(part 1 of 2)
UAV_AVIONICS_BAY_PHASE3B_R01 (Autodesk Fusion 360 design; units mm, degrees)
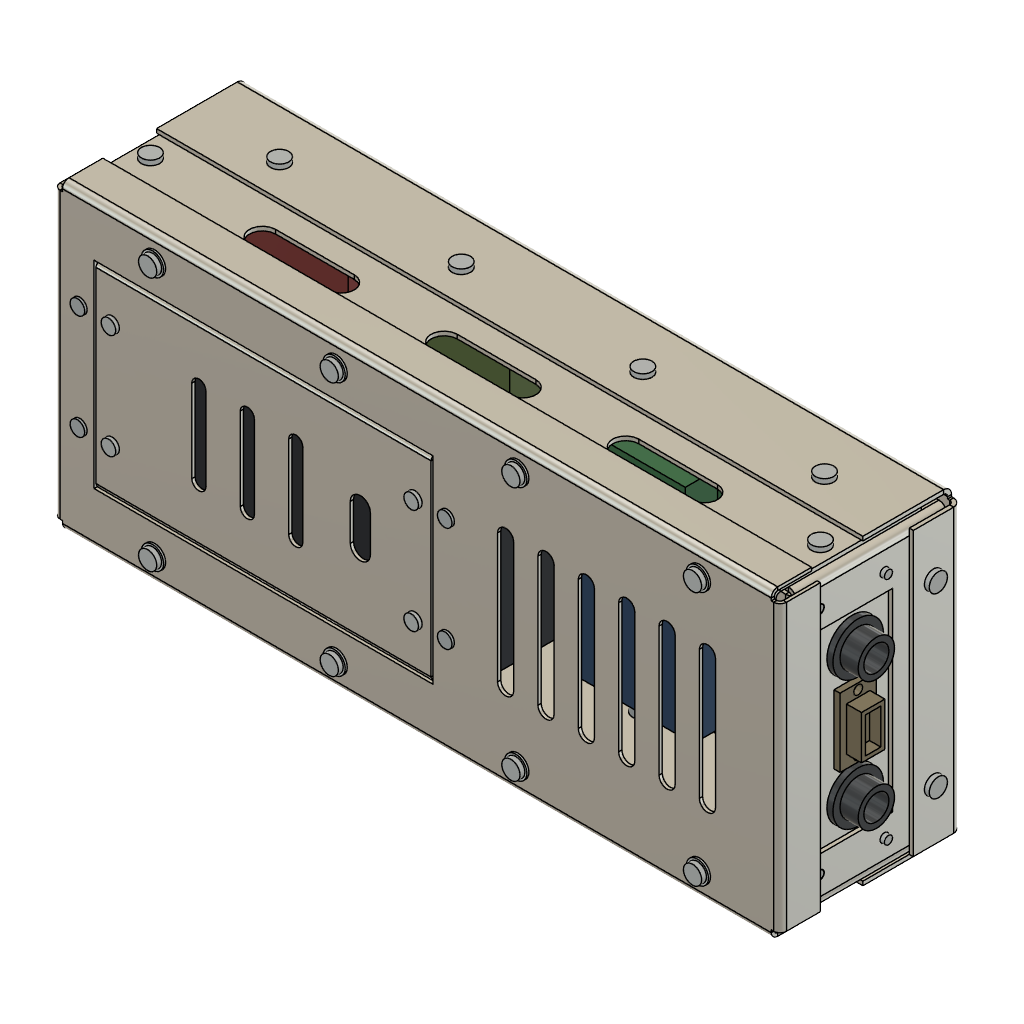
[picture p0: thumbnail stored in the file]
part number: 2026-11-24-00-18-26-593
part number: 2026-11-24-00-18-26-798
part number: 2026-11-24-00-18-26-808
part number: 2026-11-24-00-18-26-817
part number: 2026-11-24-00-18-26-829
part number: 2026-11-24-00-18-26-839
part number: 2026-11-24-00-18-26-851
part number: 2026-11-24-00-18-26-863
part number: 2026-11-24-00-18-26-875
part number: 2026-11-24-00-18-26-921
part number: 2026-11-24-00-18-27-862
part number: 2026-11-24-00-18-28-309
part number: 2026-11-24-00-18-28-832
part number: 2026-11-24-00-18-29-449
part number: 2026-11-24-00-18-30-126
part number: 2026-11-24-00-18-31-171
part number: 2026-11-24-00-18-31-826
part number: 2026-11-24-00-18-32-270
part number: 2026-11-24-00-18-33-121
part number: 2026-11-24-00-18-33-465
parameter "BAY_LENGTH" = 180 comment "[Assumption] Concept avionics bay overall outer length (X)"
parameter "BAY_WIDTH" = 75 comment "[Assumption] Concept avionics bay overall outer width (Y)"
parameter "BAY_HEIGHT" = 45 comment "[Assumption] Concept avionics bay overall outer height (Z)"
parameter "TRAY_FLANGE_H" = 22 comment "[Preliminary] Base tray perimeter upward flange height"
parameter "COVER_SKIRT_H" = 10 comment "[Preliminary] Top cover downward perimeter skirt height"
parameter "FORWARD_ZONE_END_X" = 94 comment "[Preliminary] X-boundary separating battery zone and aft deck"
parameter "HATCH_LENGTH" = 84 comment "[Preliminary] Service access hatch opening length"
parameter "HATCH_WIDTH" = 49 comment "[Preliminary] Service access hatch opening width"
parameter "T_BASE_TRAY" = 1 comment "[Preliminary] Main folded base tray thickness"
parameter "T_TOP_COVER" = 0.8 comment "[Preliminary] Removable top cover thickness"
parameter "T_ACCESS_HATCH" = 0.8 comment "[Preliminary] Service access hatch thickness"
parameter "T_SIDE_RAIL" = 1 comment "[Preliminary] Left and right side support rails thickness"
parameter "T_BULKHEAD" = 1 comment "[Preliminary] Front, rear, and connector bulkheads thickness"
parameter "T_EQUIP_DECK" = 1 comment "[Preliminary] Removable internal equipment deck thickness"
parameter "T_BRACKET" = 1 comment "[Preliminary] Structural and retention brackets thickness"
parameter "T_CABLE_CH" = 0.8 comment "[Preliminary] Cable routing channel and clamp thickness"
parameter "BEND_R_1_0" = 1 comment "[Preliminary] Inside bend radius for 1.0 mm Al 5052-H32"
parameter "BEND_R_0_8" = 0.8 comment "[Preliminary] Inside bend radius for 0.8 mm Al 5052-H32"
parameter "RELIEF_W_1_0" = 1.5 comment "[Preliminary] Bend relief width for 1.0 mm sheet"
parameter "RELIEF_D_1_0" = 2.5 comment "[Preliminary] Bend relief depth for 1.0 mm sheet"
parameter "RELIEF_W_0_8" = 1.2 comment "[Preliminary] Bend relief width for 0.8 mm sheet"
parameter "RELIEF_D_0_8" = 2.1 comment "[Preliminary] Bend relief depth for 0.8 mm sheet"
parameter "HOLE_CLR_M2_0" = 2.2 comment "[Preliminary] M2.0 medium clearance hole diameter"
parameter "HOLE_CLR_M2_5" = 2.7 comment "[Preliminary] M2.5 medium clearance hole diameter"
parameter "HOLE_CLR_M3_0" = 3.4 comment "[Preliminary] M3.0 medium clearance hole diameter"
parameter "HEAD_DIA_M2_0" = 3.8 comment "[Preliminary] ISO 4762/7380 M2.0 head diameter"
parameter "HEAD_DIA_M2_5" = 4.5 comment "[Preliminary] ISO 4762/7380 M2.5 head diameter"
parameter "STANDOFF_DECK_H" = 6 comment "[Preliminary] Under-deck plenum standoff height"
parameter "STANDOFF_PCB_H" = 4 comment "[Preliminary] PCB mounting standoff height"
parameter "ISO_PAD_THICK" = 2 comment "[Preliminary] Battery elastomer isolation pad thickness"
parameter "CLR_EQUIP_WALL" = 2 comment "[Preliminary] Minimum clearance between electronics and walls"
parameter "CLR_COMPONENT" = 1.5 comment "[Preliminary] General minimum clearance between adjacent parts"
parameter "CLR_SLIP_FIT" = 0.25 comment "[Preliminary] Per-side slip clearance for nested sheet metal parts"
parameter "CLR_COVER_FIT" = 0.3 comment "[Preliminary] Per-side clearance between cover skirt and chassis"
parameter "CLR_HATCH_GAP" = 0.5 comment "[Preliminary] Perimeter gap around removable service hatch"
parameter "d37" = 2
parameter "d38" = 1
parameter "d39" = 0.8
place_component sketch "SK_PCB_Substrate"
place_component sketch "SK_PCB_Substrate"
place_component sketch "SK_PCB_Substrate"
place_component sketch "SK_PCB_Substrate"
place_component sketch "SK_PCB_Substrate"
place_component sketch "SK_PCB_Substrate"
place_component sketch "SK_PCB_Substrate"
place_component sketch "SK_PCB_Substrate"
place_component sketch "SK_PCB_Substrate"
sketch "SK_Base_Tray_Blank" plane through (0, 0, 0) normal (0, 0, 1) x axis (1, 0, 0)
  line L1 (177.5, -37.5) -> (2.5, -37.5)
  line L2 (177.5, -35) -> (177.5, -37.5)
  line L3 (180, -35) -> (177.5, -35)
  line L4 (180, 35) -> (180, -35)
  line L5 (177.5, 35) -> (180, 35)
  line L6 (177.5, 37.5) -> (177.5, 35)
  line L7 (2.5, 37.5) -> (177.5, 37.5)
  line L8 (2.5, 35) -> (2.5, 37.5)
  line L9 (0, 35) -> (2.5, 35)
  line L10 (0, -35) -> (0, 35)
  line L11 (2.5, -35) -> (0, -35)
  line L12 (2.5, -37.5) -> (2.5, -35)
face "BaseFlange1" sketch "SK_Base_Tray_Blank"
face "EdgeFlange2" FlangeHeight 22 FlangeAngle 90
face "EdgeFlange3" FlangeHeight 12 FlangeAngle 90
sketch "SK_Base_Tray_Floor_Cutouts" plane through (0, 0, 0) normal (0, 0, 1) x axis (1, 0, 0)
  line L1 (27.3, -24.3) -> (22.7, -24.3)
  line L2 (22.7, -27.7) -> (27.3, -27.7)
  line L3 (27.3, 27.7) -> (22.7, 27.7)
  line L4 (22.7, 24.3) -> (27.3, 24.3)
  line L5 (157.3, -24.3) -> (152.7, -24.3)
  line L6 (152.7, -27.7) -> (157.3, -27.7)
  line L7 (157.3, 27.7) -> (152.7, 27.7)
  line L8 (152.7, 24.3) -> (157.3, 24.3)
  line L9 (64.5, -11.5) -> (35.5, -11.5)
  line L10 (35.5, -18.5) -> (64.5, -18.5)
  line L11 (149.5, 3.5) -> (120.5, 3.5)
  line L12 (120.5, -3.5) -> (149.5, -3.5)
  arc A1 centre (27.3, -26) radius 1.7 clockwise from (27.3, -24.3) to (27.3, -27.7)
  arc A2 centre (22.7, -26) radius 1.7 clockwise from (22.7, -27.7) to (22.7, -24.3)
  arc A3 centre (27.3, 26) radius 1.7 clockwise from (27.3, 27.7) to (27.3, 24.3)
  arc A4 centre (22.7, 26) radius 1.7 clockwise from (22.7, 24.3) to (22.7, 27.7)
  arc A5 centre (157.3, -26) radius 1.7 clockwise from (157.3, -24.3) to (157.3, -27.7)
  arc A6 centre (152.7, -26) radius 1.7 clockwise from (152.7, -27.7) to (152.7, -24.3)
  arc A7 centre (157.3, 26) radius 1.7 clockwise from (157.3, 27.7) to (157.3, 24.3)
  arc A8 centre (152.7, 26) radius 1.7 clockwise from (152.7, 24.3) to (152.7, 27.7)
  circle C1 centre (99, -29) radius 1.35
  circle C2 centre (99, 29) radius 1.35
  circle C3 centre (166, -29) radius 1.35
  circle C4 centre (166, 29) radius 1.35
  circle C5 centre (14, -27) radius 1.35
  circle C6 centre (14, -3) radius 1.35
  circle C7 centre (86, -27) radius 1.35
  circle C8 centre (86, -3) radius 1.35
  circle C9 centre (112, 12.5) radius 1.1
  circle C10 centre (152, 12.5) radius 1.1
  circle C11 centre (110, -17.5) radius 1.1
  circle C12 centre (134, -17.5) radius 1.1
  circle C13 centre (158, -17.5) radius 1.1
  circle C14 centre (13, 11) radius 1.1
  circle C15 centre (13, 27) radius 1.1
  circle C16 centre (45, 11) radius 1.1
  circle C17 centre (45, 27) radius 1.1
  circle C18 centre (57, 11) radius 1.1
  circle C19 centre (57, 27) radius 1.1
  circle C20 centre (85, 11) radius 1.1
  circle C21 centre (85, 27) radius 1.1
  arc A9 centre (64.5, -15) radius 3.5 clockwise from (64.5, -11.5) to (64.5, -18.5)
  arc A10 centre (35.5, -15) radius 3.5 clockwise from (35.5, -18.5) to (35.5, -11.5)
  arc A11 centre (149.5, 0) radius 3.5 clockwise from (149.5, 3.5) to (149.5, -3.5)
  arc A12 centre (120.5, 0) radius 3.5 clockwise from (120.5, -3.5) to (120.5, 3.5)
extrude "Extrude1" cut sketch "SK_Base_Tray_Floor_Cutouts" distance 2
work_plane "WorkPlane1" AlongDistance -37.5 ExtraOffset 0
sketch "SK_Tray_Left_Wall_Holes" plane through (0, -37.5, 0) normal (0, 1, 0) x axis (1, 0, 0)
  circle C1 centre (25, -14) radius 1.35
  circle C2 centre (70, -14) radius 1.35
  circle C3 centre (115, -14) radius 1.35
  circle C4 centre (160, -14) radius 1.35
extrude "Extrude2" cut sketch "SK_Tray_Left_Wall_Holes" distance 2
work_plane "WorkPlane2" AlongDistance 37.5 ExtraOffset 0
sketch "SK_Tray_Right_Wall_Holes" plane through (0, 37.5, 0) normal (0, 1, 0) x axis (1, 0, 0)
  circle C1 centre (25, -14) radius 1.35
  circle C2 centre (70, -14) radius 1.35
  circle C3 centre (115, -14) radius 1.35
  circle C4 centre (160, -14) radius 1.35
extrude "Extrude3" cut sketch "SK_Tray_Right_Wall_Holes" distance 2
sketch "SK_Tray_Front_Lip_Holes" plane through (0, 0, 0) normal (1, 0, 0) x axis (0, 0, -1)
  circle C1 centre (-7, -22) radius 1.35
  circle C2 centre (-7, 22) radius 1.35
extrude "Extrude4" cut sketch "SK_Tray_Front_Lip_Holes" distance 2
work_plane "WorkPlane3" AlongDistance 180 ExtraOffset 0
sketch "SK_Tray_Rear_Lip_Holes" plane through (180, 0, 0) normal (1, 0, 0) x axis (0, 0, -1)
  circle C1 centre (-7, -22) radius 1.35
  circle C2 centre (-7, 22) radius 1.35
extrude "Extrude5" cut sketch "SK_Tray_Rear_Lip_Holes" distance 2
place_component sketch "SK_PCB_Substrate"
work_plane "WorkPlane1" AlongDistance -36.35 ExtraOffset 0
sketch "SK_PDB-01-102_Left_Side_Rail_Web" plane through (0, -36.35, 0) normal (0, 1, 0) x axis (1, 0, 0)
  line L1 (177, -7) -> (3, -7)
  line L2 (177, -44) -> (177, -7)
  line L3 (3, -44) -> (177, -44)
  line L4 (3, -7) -> (3, -44)
face "BaseFlange1" sketch "SK_PDB-01-102_Left_Side_Rail_Web"
face "EdgeFlange2" FlangeHeight 9 FlangeAngle 90
sketch "SK_PDB-01-102_Left_Side_Rail_Web_Features" plane through (0, -36.35, 0) normal (0, 1, 0) x axis (1, 0, 0)
  line L1 (57.25, -34.25) -> (37.75, -34.25)
  line L2 (37.75, -27.75) -> (57.25, -27.75)
  line L3 (102.25, -34.25) -> (82.75, -34.25)
  line L4 (82.75, -27.75) -> (102.25, -27.75)
  line L5 (147.25, -34.25) -> (127.75, -34.25)
  line L6 (127.75, -27.75) -> (147.25, -27.75)
  circle C1 centre (25, -14) radius 1.35
  circle C2 centre (70, -14) radius 1.35
  circle C3 centre (115, -14) radius 1.35
  circle C4 centre (160, -14) radius 1.35
  circle C5 centre (7, -28) radius 1.35
  circle C6 centre (173, -28) radius 1.35
  arc A1 centre (57.25, -31) radius 3.25 clockwise from (57.25, -27.75) to (57.25, -34.25)
  arc A2 centre (37.75, -31) radius 3.25 clockwise from (37.75, -34.25) to (37.75, -27.75)
  arc A3 centre (102.25, -31) radius 3.25 clockwise from (102.25, -27.75) to (102.25, -34.25)
  arc A4 centre (82.75, -31) radius 3.25 clockwise from (82.75, -34.25) to (82.75, -27.75)
  arc A5 centre (147.25, -31) radius 3.25 clockwise from (147.25, -27.75) to (147.25, -34.25)
  arc A6 centre (127.75, -31) radius 3.25 clockwise from (127.75, -34.25) to (127.75, -27.75)
extrude "Extrude1" cut sketch "SK_PDB-01-102_Left_Side_Rail_Web_Features" distance 2
work_plane "WorkPlane2" AlongDistance 44 ExtraOffset 0
sketch "SK_PDB-01-102_Left_Side_Rail_Top_Holes" plane through (0, 0, 44) normal (0, 0, 1) x axis (1, 0, 0)
  circle C1 centre (25, -31.5) radius 1.35
  circle C2 centre (70, -31.5) radius 1.35
  circle C3 centre (115, -31.5) radius 1.35
  circle C4 centre (160, -31.5) radius 1.35
extrude "Extrude2" cut sketch "SK_PDB-01-102_Left_Side_Rail_Top_Holes" distance 2
place_component sketch "SK_PCB_Substrate"
work_plane "WorkPlane1" AlongDistance 36.35 ExtraOffset 0
sketch "SK_PDB-01-103_Right_Side_Rail_Web" plane through (0, 36.35, 0) normal (0, 1, 0) x axis (1, 0, 0)
  line L1 (177, -7) -> (3, -7)
  line L2 (177, -44) -> (177, -7)
  line L3 (3, -44) -> (177, -44)
  line L4 (3, -7) -> (3, -44)
face "BaseFlange2" sketch "SK_PDB-01-103_Right_Side_Rail_Web"
face "EdgeFlange3" FlangeHeight 9 FlangeAngle 90
sketch "SK_PDB-01-103_Right_Side_Rail_Web_Features" plane through (0, 36.35, 0) normal (0, 1, 0) x axis (1, 0, 0)
  line L1 (57.25, -34.25) -> (37.75, -34.25)
  line L2 (37.75, -27.75) -> (57.25, -27.75)
  line L3 (102.25, -34.25) -> (82.75, -34.25)
  line L4 (82.75, -27.75) -> (102.25, -27.75)
  line L5 (147.25, -34.25) -> (127.75, -34.25)
  line L6 (127.75, -27.75) -> (147.25, -27.75)
  circle C1 centre (25, -14) radius 1.35
  circle C2 centre (70, -14) radius 1.35
  circle C3 centre (115, -14) radius 1.35
  circle C4 centre (160, -14) radius 1.35
  circle C5 centre (7, -28) radius 1.35
  circle C6 centre (173, -28) radius 1.35
  arc A1 centre (57.25, -31) radius 3.25 clockwise from (57.25, -27.75) to (57.25, -34.25)
  arc A2 centre (37.75, -31) radius 3.25 clockwise from (37.75, -34.25) to (37.75, -27.75)
  arc A3 centre (102.25, -31) radius 3.25 clockwise from (102.25, -27.75) to (102.25, -34.25)
  arc A4 centre (82.75, -31) radius 3.25 clockwise from (82.75, -34.25) to (82.75, -27.75)
  arc A5 centre (147.25, -31) radius 3.25 clockwise from (147.25, -27.75) to (147.25, -34.25)
  arc A6 centre (127.75, -31) radius 3.25 clockwise from (127.75, -34.25) to (127.75, -27.75)
extrude "Extrude1" cut sketch "SK_PDB-01-103_Right_Side_Rail_Web_Features" distance 2
work_plane "WorkPlane2" AlongDistance 44 ExtraOffset 0
sketch "SK_PDB-01-103_Right_Side_Rail_Top_Holes" plane through (0, 0, 44) normal (0, 0, 1) x axis (1, 0, 0)
  circle C1 centre (25, 31.5) radius 1.35
  circle C2 centre (70, 31.5) radius 1.35
  circle C3 centre (115, 31.5) radius 1.35
  circle C4 centre (160, 31.5) radius 1.35
extrude "Extrude2" cut sketch "SK_PDB-01-103_Right_Side_Rail_Top_Holes" distance 2
place_component sketch "SK_PCB_Substrate"
work_plane "WorkPlane1" AlongDistance 1.15 ExtraOffset 0
sketch "SK_Front_Bulkhead_Blank" plane through (1.15, 0, 0) normal (1, 0, 0) x axis (0, 0, -1)
  line L1 (-2.5, 35.2) -> (-2.5, -35.2)
  line L2 (-39.8, 35.2) -> (-2.5, 35.2)
  line L3 (-39.8, 32.2) -> (-39.8, 35.2)
  line L4 (-42.8, 32.2) -> (-39.8, 32.2)
  line L5 (-42.8, -32.2) -> (-42.8, 32.2)
  line L6 (-39.8, -32.2) -> (-42.8, -32.2)
  line L7 (-39.8, -35.2) -> (-39.8, -32.2)
  line L8 (-2.5, -35.2) -> (-39.8, -35.2)
face "BaseFlange1" sketch "SK_Front_Bulkhead_Blank"
face "EdgeFlange2" FlangeHeight 10 FlangeAngle 90
face "EdgeFlange3" FlangeHeight 8 FlangeAngle 90
sketch "SK_Front_Bulkhead_Cutouts" plane through (1.15, 0, 0) normal (1, 0, 0) x axis (0, 0, -1)
  line L1 (-26.5, -16.5) -> (-26.5, -23.5)
  line L2 (-21.5, -23.5) -> (-21.5, -16.5)
  line L3 (-26.5, 23.5) -> (-26.5, 16.5)
  line L4 (-21.5, 16.5) -> (-21.5, 23.5)
  circle C1 centre (-7, -22) radius 1.35
  circle C2 centre (-7, 22) radius 1.35
  circle C3 centre (-24, 0) radius 5
  circle C4 centre (-24, -9) radius 1.1
  circle C5 centre (-24, 9) radius 1.1
  arc A1 centre (-24, -16.5) radius 2.5 clockwise from (-26.5, -16.5) to (-21.5, -16.5)
  arc A2 centre (-24, -23.5) radius 2.5 clockwise from (-21.5, -23.5) to (-26.5, -23.5)
  arc A3 centre (-24, 23.5) radius 2.5 clockwise from (-26.5, 23.5) to (-21.5, 23.5)
  arc A4 centre (-24, 16.5) radius 2.5 clockwise from (-21.5, 16.5) to (-26.5, 16.5)
extrude "Extrude1" cut sketch "SK_Front_Bulkhead_Cutouts" distance 2
work_plane "WorkPlane2" AlongDistance -35.2 ExtraOffset 0
sketch "SK_Front_Left_Hole" plane through (0, -35.2, 0) normal (0, 1, 0) x axis (1, 0, 0)
  circle C1 centre (7, -28) radius 1.35
extrude "Extrude2" cut sketch "SK_Front_Left_Hole" distance 2
work_plane "WorkPlane3" AlongDistance 35.2 ExtraOffset 0
sketch "SK_Front_Right_Hole" plane through (0, 35.2, 0) normal (0, 1, 0) x axis (1, 0, 0)
  circle C1 centre (7, -28) radius 1.35
extrude "Extrude3" cut sketch "SK_Front_Right_Hole" distance 2
place_component sketch "SK_PCB_Substrate"
work_plane "WorkPlane1" AlongDistance 178.85 ExtraOffset 0
sketch "SK_Rear_Bulkhead_Blank" plane through (178.85, 0, 0) normal (1, 0, 0) x axis (0, 0, -1)
  line L1 (-2.5, 35.2) -> (-2.5, -35.2)
  line L2 (-39.8, 35.2) -> (-2.5, 35.2)
  line L3 (-39.8, 32.2) -> (-39.8, 35.2)
  line L4 (-42.8, 32.2) -> (-39.8, 32.2)
  line L5 (-42.8, -32.2) -> (-42.8, 32.2)
  line L6 (-39.8, -32.2) -> (-42.8, -32.2)
  line L7 (-39.8, -35.2) -> (-39.8, -32.2)
  line L8 (-2.5, -35.2) -> (-39.8, -35.2)
face "BaseFlange2" sketch "SK_Rear_Bulkhead_Blank"
face "EdgeFlange3" FlangeHeight 10 FlangeAngle 90
face "EdgeFlange4" FlangeHeight 8 FlangeAngle 90
sketch "SK_Rear_Bulkhead_Cutouts" plane through (178.85, 0, 0) normal (1, 0, 0) x axis (0, 0, -1)
  line L1 (-16, 24) -> (-16, -24)
  line L2 (-36, 24) -> (-16, 24)
  line L3 (-36, -24) -> (-36, 24)
  line L4 (-16, -24) -> (-36, -24)
  circle C1 centre (-7, -22) radius 1.35
  circle C2 centre (-7, 22) radius 1.35
  circle C3 centre (-18, -28.5) radius 1.1
  circle C4 centre (-34, -28.5) radius 1.1
  circle C5 centre (-18, 28.5) radius 1.1
  circle C6 centre (-34, 28.5) radius 1.1
extrude "Extrude1" cut sketch "SK_Rear_Bulkhead_Cutouts" distance 2
work_plane "WorkPlane2" AlongDistance -35.2 ExtraOffset 0
sketch "SK_Rear_Left_Hole" plane through (0, -35.2, 0) normal (0, 1, 0) x axis (1, 0, 0)
  circle C1 centre (173, -28) radius 1.35
extrude "Extrude2" cut sketch "SK_Rear_Left_Hole" distance 2
work_plane "WorkPlane3" AlongDistance 35.2 ExtraOffset 0
sketch "SK_Rear_Right_Hole" plane through (0, 35.2, 0) normal (0, 1, 0) x axis (1, 0, 0)
  circle C1 centre (173, -28) radius 1.35
extrude "Extrude3" cut sketch "SK_Rear_Right_Hole" distance 2
place_component sketch "SK_PCB_Substrate"
work_plane "WorkPlane1" AlongDistance 45 ExtraOffset 0
sketch "SK_Top_Cover_Blank" plane through (0, 0, 45) normal (0, 0, 1) x axis (1, 0, 0)
  line L1 (177.8, -37.5) -> (2.2, -37.5)
  line L2 (177.8, -35.3) -> (177.8, -37.5)
  line L3 (180, -35.3) -> (177.8, -35.3)
  line L4 (180, 35.3) -> (180, -35.3)
  line L5 (177.8, 35.3) -> (180, 35.3)
  line L6 (177.8, 37.5) -> (177.8, 35.3)
  line L7 (2.2, 37.5) -> (177.8, 37.5)
  line L8 (2.2, 35.3) -> (2.2, 37.5)
  line L9 (0, 35.3) -> (2.2, 35.3)
  line L10 (0, -35.3) -> (0, 35.3)
  line L11 (2.2, -35.3) -> (0, -35.3)
  line L12 (2.2, -37.5) -> (2.2, -35.3)
face "BaseFlange2" sketch "SK_Top_Cover_Blank"
face "EdgeFlange3" FlangeHeight 10 FlangeAngle 90
face "EdgeFlange4" FlangeHeight 10 FlangeAngle 90
sketch "SK_Top_Cover_Cutouts" plane through (0, 0, 45) normal (0, 0, 1) x axis (1, 0, 0)
  line L1 (94, -24.5) -> (10, -24.5)
  line L2 (94, 24.5) -> (94, -24.5)
  line L3 (10, 24.5) -> (94, 24.5)
  line L4 (10, -24.5) -> (10, 24.5)
  line L5 (114, 16) -> (114, -16)
  line L6 (110, -16) -> (110, 16)
  line L7 (124, 16) -> (124, -16)
  line L8 (120, -16) -> (120, 16)
  line L9 (134, 16) -> (134, -16)
  line L10 (130, -16) -> (130, 16)
  line L11 (144, 16) -> (144, -16)
  line L12 (140, -16) -> (140, 16)
  line L13 (154, 16) -> (154, -16)
  line L14 (150, -16) -> (150, 16)
  line L15 (164, 16) -> (164, -16)
  line L16 (160, -16) -> (160, 16)
  circle C1 centre (25, -31.5) radius 1.35
  circle C2 centre (25, 31.5) radius 1.35
  circle C3 centre (70, -31.5) radius 1.35
  circle C4 centre (70, 31.5) radius 1.35
  circle C5 centre (115, -31.5) radius 1.35
  circle C6 centre (115, 31.5) radius 1.35
  circle C7 centre (160, -31.5) radius 1.35
  circle C8 centre (160, 31.5) radius 1.35
  circle C9 centre (6.5, -13) radius 1.1
  circle C10 centre (6.5, 13) radius 1.1
  circle C11 centre (97.5, -13) radius 1.1
  circle C12 centre (97.5, 13) radius 1.1
  arc A1 centre (112, 16) radius 2 clockwise from (110, 16) to (114, 16)
  arc A2 centre (112, -16) radius 2 clockwise from (114, -16) to (110, -16)
  arc A3 centre (122, 16) radius 2 clockwise from (120, 16) to (124, 16)
  arc A4 centre (122, -16) radius 2 clockwise from (124, -16) to (120, -16)
  arc A5 centre (132, 16) radius 2 clockwise from (130, 16) to (134, 16)
  arc A6 centre (132, -16) radius 2 clockwise from (134, -16) to (130, -16)
  arc A7 centre (142, 16) radius 2 clockwise from (140, 16) to (144, 16)
  arc A8 centre (142, -16) radius 2 clockwise from (144, -16) to (140, -16)
  arc A9 centre (152, 16) radius 2 clockwise from (150, 16) to (154, 16)
  arc A10 centre (152, -16) radius 2 clockwise from (154, -16) to (150, -16)
  arc A11 centre (162, 16) radius 2 clockwise from (160, 16) to (164, 16)
  arc A12 centre (162, -16) radius 2 clockwise from (164, -16) to (160, -16)
extrude "Extrude1" cut sketch "SK_Top_Cover_Cutouts" distance 2
place_component sketch "SK_PCB_Substrate"
work_plane "WorkPlane1" AlongDistance 45 ExtraOffset 0
sketch "SK_Access_Hatch_Blank" plane through (0, 0, 45) normal (0, 0, 1) x axis (1, 0, 0)
  line L1 (93.5, -24) -> (10.5, -24)
  line L2 (93.5, 24) -> (93.5, -24)
  line L3 (10.5, 24) -> (93.5, 24)
  line L4 (10.5, -24) -> (10.5, 24)
face "BaseFlange2" sketch "SK_Access_Hatch_Blank"
face "Hem3" HemGap 0.02 HemLength 4.5
face "Hem4" HemGap 0.02 HemLength 4.5
sketch "SK_Access_Hatch_Cutouts" plane through (0, 0, 45) normal (0, 0, 1) x axis (1, 0, 0)
  line L1 (37.75, 10.25) -> (37.75, -10.25)
  line L2 (34.25, -10.25) -> (34.25, 10.25)
  line L3 (49.75, 10.25) -> (49.75, -10.25)
  line L4 (46.25, -10.25) -> (46.25, 10.25)
  line L5 (61.75, 10.25) -> (61.75, -10.25)
  line L6 (58.25, -10.25) -> (58.25, 10.25)
  line L7 (78.5, 4.5) -> (78.5, -4.5)
  line L8 (73.5, -4.5) -> (73.5, 4.5)
  circle C1 centre (14.5, -13) radius 1.1
  circle C2 centre (14.5, 13) radius 1.1
  circle C3 centre (89.5, -13) radius 1.1
  circle C4 centre (89.5, 13) radius 1.1
  arc A1 centre (36, 10.25) radius 1.75 clockwise from (34.25, 10.25) to (37.75, 10.25)
  arc A2 centre (36, -10.25) radius 1.75 clockwise from (37.75, -10.25) to (34.25, -10.25)
  arc A3 centre (48, 10.25) radius 1.75 clockwise from (46.25, 10.25) to (49.75, 10.25)
  arc A4 centre (48, -10.25) radius 1.75 clockwise from (49.75, -10.25) to (46.25, -10.25)
  arc A5 centre (60, 10.25) radius 1.75 clockwise from (58.25, 10.25) to (61.75, 10.25)
  arc A6 centre (60, -10.25) radius 1.75 clockwise from (61.75, -10.25) to (58.25, -10.25)
  arc A7 centre (76, 4.5) radius 2.5 clockwise from (73.5, 4.5) to (78.5, 4.5)
  arc A8 centre (76, -4.5) radius 2.5 clockwise from (78.5, -4.5) to (73.5, -4.5)
extrude "Extrude1" cut sketch "SK_Access_Hatch_Cutouts" distance 2
place_component sketch "SK_PCB_Substrate"
work_plane "WorkPlane1" AlongDistance 44.2 ExtraOffset 0
sketch "SK_Retainer_Strip_Blank" plane through (0, 0, 44.2) normal (0, 0, 1) x axis (1, 0, 0)
  line L1 (18, -18) -> (3, -18)
  line L2 (18, 18) -> (18, -18)
  line L3 (3, 18) -> (18, 18)
  line L4 (3, -18) -> (3, 18)
face "BaseFlange2" sketch "SK_Retainer_Strip_Blank"
sketch "SK_Retainer_Strip_Holes" plane through (0, 0, 44.2) normal (0, 0, 1) x axis (1, 0, 0)
  circle C1 centre (6.5, -13) radius 1.1
  circle C2 centre (6.5, 13) radius 1.1
  circle C3 centre (14.5, -13) radius 1.1
  circle C4 centre (14.5, 13) radius 1.1
extrude "Extrude1" cut sketch "SK_Retainer_Strip_Holes" distance 2
copy_paste "CopyPaste1"
place_component sketch "SK_PCB_Substrate"
work_plane "WorkPlane1" AlongDistance 7 ExtraOffset 0
sketch "SK_Equipment_Deck_Blank" plane through (0, 0, 7) normal (0, 0, 1) x axis (1, 0, 0)
  line L1 (174, -33.5) -> (94, -33.5)
  line L2 (174, 33.5) -> (174, -33.5)
  line L3 (94, 33.5) -> (174, 33.5)
  line L4 (94, -33.5) -> (94, 33.5)
face "BaseFlange1" sketch "SK_Equipment_Deck_Blank"
face "EdgeFlange2" FlangeHeight 6 FlangeAngle 90
sketch "SK_Equipment_Deck_Cutouts" plane through (0, 0, 7) normal (0, 0, 1) x axis (1, 0, 0)
  line L1 (131.5, -10) -> (115.5, -10)
  line L2 (115.5, -16) -> (131.5, -16)
  line L3 (144.75, 23) -> (144.75, 11)
  line L4 (140.75, 11) -> (140.75, 23)
  circle C1 centre (99, -29) radius 1.35
  circle C2 centre (99, 29) radius 1.35
  circle C3 centre (166, -29) radius 1.35
  circle C4 centre (166, 29) radius 1.35
  circle C5 centre (106, -28) radius 1.1
  circle C6 centre (106, 2) radius 1.1
  circle C7 centre (141, -28) radius 1.1
  circle C8 centre (141, 2) radius 1.1
  circle C9 centre (105.5, 12) radius 1.1
  circle C10 centre (105.5, 28) radius 1.1
  circle C11 centre (135.5, 12) radius 1.1
  circle C12 centre (135.5, 28) radius 1.1
  circle C13 centre (150, -22) radius 1.1
  circle C14 centre (150, -4) radius 1.1
  circle C15 centre (168, -22) radius 1.1
  circle C16 centre (168, -4) radius 1.1
  circle C17 centre (150, 5) radius 1.1
  circle C18 centre (150, 23) radius 1.1
  circle C19 centre (168, 5) radius 1.1
  circle C20 centre (168, 23) radius 1.1
  arc A1 centre (131.5, -13) radius 3 clockwise from (131.5, -10) to (131.5, -16)
  arc A2 centre (115.5, -13) radius 3 clockwise from (115.5, -16) to (115.5, -10)
  arc A3 centre (142.75, 23) radius 2 clockwise from (140.75, 23) to (144.75, 23)
  arc A4 centre (142.75, 11) radius 2 clockwise from (144.75, 11) to (140.75, 11)
extrude "Extrude1" cut sketch "SK_Equipment_Deck_Cutouts" distance 2
sketch "SK_PCB_Clamp_Blank" plane through (0, 0, 0) normal (0, 0, 1) x axis (1, 0, 0)
  line L1 (3, -17.5) -> (-4, -17.5)
  line L2 (3, 17.5) -> (3, -17.5)
  line L3 (-4, 17.5) -> (3, 17.5)
  line L4 (-4, -17.5) -> (-4, 17.5)
face "BaseFlange1" sketch "SK_PCB_Clamp_Blank"
face "EdgeFlange2" FlangeHeight 6 FlangeAngle 90
sketch "SK_PCB_Clamp_Holes" plane through (0, 0, 0) normal (0, 0, 1) x axis (1, 0, 0)
  circle C1 centre (0, -15) radius 1.1
  circle C2 centre (0, 15) radius 1.1
extrude "Extrude1" cut sketch "SK_PCB_Clamp_Holes" distance 2
copy_paste "CopyPaste1"
place_component sketch "SK_PDB-03-303_Deck_Standoff_M2_5x6_Body"
sketch "SK_PDB-03-303_Deck_Standoff_M2_5x6_Body" plane through (0, 0, 0) normal (0, 0, 1) x axis (1, 0, 0)
  circle C1 centre (0, 0) radius 2.5
  circle C2 centre (0, 0) radius 1.3
extrude "Extrude1" new body sketch "SK_PDB-03-303_Deck_Standoff_M2_5x6_Body" along normal blind 6
copy_paste "CopyPaste2"
copy_paste "CopyPaste3"
copy_paste "CopyPaste4"
place_component sketch "SK_PDB-03-304_PCB_Standoff_M2x4_Body"
sketch "SK_PDB-03-304_PCB_Standoff_M2x4_Body" plane through (0, 0, 0) normal (0, 0, 1) x axis (1, 0, 0)
  circle C1 centre (0, 0) radius 2
  circle C2 centre (0, 0) radius 1.05
extrude "Extrude1" new body sketch "SK_PDB-03-304_PCB_Standoff_M2x4_Body" along normal blind 4
copy_paste "CopyPaste5"
copy_paste "CopyPaste6"
copy_paste "CopyPaste7"
copy_paste "CopyPaste8"
copy_paste "CopyPaste9"
copy_paste "CopyPaste10"
copy_paste "CopyPaste11"
copy_paste "CopyPaste12"
copy_paste "CopyPaste13"
copy_paste "CopyPaste14"
copy_paste "CopyPaste15"
copy_paste "CopyPaste16"
copy_paste "CopyPaste17"
copy_paste "CopyPaste18"
copy_paste "CopyPaste19"
copy_paste "CopyPaste20"
copy_paste "CopyPaste21"
copy_paste "CopyPaste22"
copy_paste "CopyPaste23"
copy_paste "CopyPaste24"
copy_paste "CopyPaste25"
copy_paste "CopyPaste26"
copy_paste "CopyPaste27"
place_component sketch "SK_PCB_Substrate"
work_plane "WorkPlane1" AlongDistance 5 ExtraOffset 0
sketch "SK_PCB_Substrate" plane through (0, 0, 5) normal (0, 0, 1) x axis (1, 0, 0)
  line L1 (48, 8) -> (10, 8)
  line L2 (48, 30) -> (48, 8)
  line L3 (10, 30) -> (48, 30)
  line L4 (10, 8) -> (10, 30)
extrude "Extrude1" new body sketch "SK_PCB_Substrate" along normal blind 2
work_plane "WorkPlane2" AlongDistance 7 ExtraOffset 0
sketch "SK_Module_Housing" plane through (0, 0, 7) normal (0, 0, 1) x axis (1, 0, 0)
  line L1 (43, 13) -> (15, 13)
  line L2 (43, 25) -> (43, 13)
  line L3 (15, 25) -> (43, 25)
  line L4 (15, 13) -> (15, 25)
extrude "Extrude2" add sketch "SK_Module_Housing" along normal blind 8
work_plane "WorkPlane3" AlongDistance 5 ExtraOffset 0
sketch "SK_PCB_Mount_Holes" plane through (0, 0, 5) normal (0, 0, 1) x axis (1, 0, 0)
  circle C1 centre (13, 11) radius 1.1
  circle C2 centre (13, 27) radius 1.1
  circle C3 centre (45, 11) radius 1.1
  circle C4 centre (45, 27) radius 1.1
extrude "Extrude3" cut sketch "SK_PCB_Mount_Holes" distance 3
place_component sketch "SK_PCB_Substrate"
work_plane "WorkPlane1" AlongDistance 5 ExtraOffset 0
sketch "SK_PCB_Substrate" plane through (0, 0, 5) normal (0, 0, 1) x axis (1, 0, 0)
  line L1 (88, 8) -> (54, 8)
  line L2 (88, 30) -> (88, 8)
  line L3 (54, 30) -> (88, 30)
  line L4 (54, 8) -> (54, 30)
extrude "Extrude1" new body sketch "SK_PCB_Substrate" along normal blind 2
work_plane "WorkPlane2" AlongDistance 7 ExtraOffset 0
sketch "SK_Module_Housing" plane through (0, 0, 7) normal (0, 0, 1) x axis (1, 0, 0)
  line L1 (83, 13) -> (59, 13)
  line L2 (83, 25) -> (83, 13)
  line L3 (59, 25) -> (83, 25)
  line L4 (59, 13) -> (59, 25)
extrude "Extrude2" add sketch "SK_Module_Housing" along normal blind 8
work_plane "WorkPlane3" AlongDistance 5 ExtraOffset 0
sketch "SK_PCB_Mount_Holes" plane through (0, 0, 5) normal (0, 0, 1) x axis (1, 0, 0)
  circle C1 centre (57, 11) radius 1.1
  circle C2 centre (57, 27) radius 1.1
  circle C3 centre (85, 11) radius 1.1
  circle C4 centre (85, 27) radius 1.1
extrude "Extrude3" cut sketch "SK_PCB_Mount_Holes" distance 3
place_component sketch "SK_PCB_Substrate"
work_plane "WorkPlane1" AlongDistance 12 ExtraOffset 0
sketch "SK_PCB_Substrate" plane through (0, 0, 12) normal (0, 0, 1) x axis (1, 0, 0)
  line L1 (144.5, -31) -> (102.5, -31)
  line L2 (144.5, 5) -> (144.5, -31)
  line L3 (102.5, 5) -> (144.5, 5)
  line L4 (102.5, -31) -> (102.5, 5)
extrude "Extrude1" new body sketch "SK_PCB_Substrate" along normal blind 2
work_plane "WorkPlane2" AlongDistance 14 ExtraOffset 0
sketch "SK_Module_Housing" plane through (0, 0, 14) normal (0, 0, 1) x axis (1, 0, 0)
  line L1 (137.5, -26) -> (109.5, -26)
  line L2 (137.5, 0) -> (137.5, -26)
  line L3 (109.5, 0) -> (137.5, 0)
  line L4 (109.5, -26) -> (109.5, 0)
extrude "Extrude2" add sketch "SK_Module_Housing" along normal blind 10
work_plane "WorkPlane3" AlongDistance 12 ExtraOffset 0
sketch "SK_PCB_Mount_Holes" plane through (0, 0, 12) normal (0, 0, 1) x axis (1, 0, 0)
  circle C1 centre (106, -28) radius 1.1
  circle C2 centre (106, 2) radius 1.1
  circle C3 centre (141, -28) radius 1.1
  circle C4 centre (141, 2) radius 1.1
extrude "Extrude3" cut sketch "SK_PCB_Mount_Holes" distance 3
place_component sketch "SK_PCB_Substrate"
work_plane "WorkPlane1" AlongDistance 12 ExtraOffset 0
sketch "SK_PCB_Substrate" plane through (0, 0, 12) normal (0, 0, 1) x axis (1, 0, 0)
  line L1 (138.5, 9) -> (102.5, 9)
  line L2 (138.5, 31) -> (138.5, 9)
  line L3 (102.5, 31) -> (138.5, 31)
  line L4 (102.5, 9) -> (102.5, 31)
extrude "Extrude1" new body sketch "SK_PCB_Substrate" along normal blind 2
work_plane "WorkPlane2" AlongDistance 14 ExtraOffset 0
sketch "SK_Module_Housing" plane through (0, 0, 14) normal (0, 0, 1) x axis (1, 0, 0)
  line L1 (133.5, 14) -> (107.5, 14)
  line L2 (133.5, 26) -> (133.5, 14)
  line L3 (107.5, 26) -> (133.5, 26)
  line L4 (107.5, 14) -> (107.5, 26)
extrude "Extrude2" add sketch "SK_Module_Housing" along normal blind 8
work_plane "WorkPlane3" AlongDistance 12 ExtraOffset 0
sketch "SK_PCB_Mount_Holes" plane through (0, 0, 12) normal (0, 0, 1) x axis (1, 0, 0)
  circle C1 centre (105.5, 12) radius 1.1
  circle C2 centre (105.5, 28) radius 1.1
  circle C3 centre (135.5, 12) radius 1.1
  circle C4 centre (135.5, 28) radius 1.1
extrude "Extrude3" cut sketch "SK_PCB_Mount_Holes" distance 3
place_component sketch "SK_PCB_Substrate"
work_plane "WorkPlane1" AlongDistance 12 ExtraOffset 0
sketch "SK_PCB_Substrate" plane through (0, 0, 12) normal (0, 0, 1) x axis (1, 0, 0)
  line L1 (171, -25) -> (147, -25)
  line L2 (171, -1) -> (171, -25)
  line L3 (147, -1) -> (171, -1)
  line L4 (147, -25) -> (147, -1)
extrude "Extrude1" new body sketch "SK_PCB_Substrate" along normal blind 2
work_plane "WorkPlane2" AlongDistance 14 ExtraOffset 0
sketch "SK_Module_Housing" plane through (0, 0, 14) normal (0, 0, 1) x axis (1, 0, 0)
  line L1 (166, -20) -> (152, -20)
  line L2 (166, -6) -> (166, -20)
  line L3 (152, -6) -> (166, -6)
  line L4 (152, -20) -> (152, -6)
extrude "Extrude2" add sketch "SK_Module_Housing" along normal blind 7
work_plane "WorkPlane3" AlongDistance 12 ExtraOffset 0
sketch "SK_PCB_Mount_Holes" plane through (0, 0, 12) normal (0, 0, 1) x axis (1, 0, 0)
  circle C1 centre (150, -22) radius 1.1
  circle C2 centre (150, -4) radius 1.1
  circle C3 centre (168, -22) radius 1.1
  circle C4 centre (168, -4) radius 1.1
extrude "Extrude3" cut sketch "SK_PCB_Mount_Holes" distance 3
place_component sketch "SK_PCB_Substrate"
work_plane "WorkPlane1" AlongDistance 12 ExtraOffset 0
sketch "SK_PCB_Substrate" plane through (0, 0, 12) normal (0, 0, 1) x axis (1, 0, 0)
  line L1 (171, 2) -> (147, 2)
  line L2 (171, 26) -> (171, 2)
  line L3 (147, 26) -> (171, 26)
  line L4 (147, 2) -> (147, 26)
extrude "Extrude1" new body sketch "SK_PCB_Substrate" along normal blind 2
work_plane "WorkPlane2" AlongDistance 14 ExtraOffset 0
sketch "SK_Module_Housing" plane through (0, 0, 14) normal (0, 0, 1) x axis (1, 0, 0)
  line L1 (166, 7) -> (152, 7)
  line L2 (166, 21) -> (166, 7)
  line L3 (152, 21) -> (166, 21)
  line L4 (152, 7) -> (152, 21)
extrude "Extrude2" add sketch "SK_Module_Housing" along normal blind 6
work_plane "WorkPlane3" AlongDistance 12 ExtraOffset 0
sketch "SK_PCB_Mount_Holes" plane through (0, 0, 12) normal (0, 0, 1) x axis (1, 0, 0)
  circle C1 centre (150, 5) radius 1.1
  circle C2 centre (150, 23) radius 1.1
  circle C3 centre (168, 5) radius 1.1
  circle C4 centre (168, 23) radius 1.1
extrude "Extrude3" cut sketch "SK_PCB_Mount_Holes" distance 3
place_component sketch "SK_PCB_Substrate"
work_plane "WorkPlane1" AlongDistance 3 ExtraOffset 0
sketch "SK_Battery_Envelope_Solid" plane through (0, 0, 3) normal (0, 0, 1) x axis (1, 0, 0)
  line L1 (92, -32) -> (8, -32)
  line L2 (92, 2) -> (92, -32)
  line L3 (8, 2) -> (92, 2)
  line L4 (8, -32) -> (8, 2)
extrude "Extrude1" new body sketch "SK_Battery_Envelope_Solid" along normal blind 24
sketch "SK_Battery_Cradle_Blank" plane through (0, 0, 0) normal (0, 0, 1) x axis (1, 0, 0)
  line L1 (4, -18.2) -> (-4, -18.2)
  line L2 (4, 18.2) -> (4, -18.2)
  line L3 (-4, 18.2) -> (4, 18.2)
  line L4 (-4, -18.2) -> (-4, 18.2)
face "BaseFlange1" sketch "SK_Battery_Cradle_Blank"
face "EdgeFlange2" FlangeHeight 27 FlangeAngle 90
sketch "SK_Cradle_Floor_Holes" plane through (0, 0, 0) normal (0, 0, 1) x axis (1, 0, 0)
  circle C1 centre (0, -12) radius 1.35
  circle C2 centre (0, 12) radius 1.35
extrude "Extrude1" cut sketch "SK_Cradle_Floor_Holes" distance 2
work_plane "WorkPlane1" AlongDistance -18.2 ExtraOffset 0
sketch "SK_Cradle_Left_Slot" plane through (0, -18.2, 0) normal (0, 1, 0) x axis (1, 0, 0)
  line L1 (1.6, -19.9) -> (1.6, -9.1)
  line L2 (-1.6, -9.1) -> (-1.6, -19.9)
  arc A1 centre (0, -19.9) radius 1.6 clockwise from (1.6, -19.9) to (-1.6, -19.9)
  arc A2 centre (0, -9.1) radius 1.6 clockwise from (-1.6, -9.1) to (1.6, -9.1)
extrude "Extrude2" cut sketch "SK_Cradle_Left_Slot" distance 2
work_plane "WorkPlane2" AlongDistance 18.2 ExtraOffset 0
sketch "SK_Cradle_Right_Slot" plane through (0, 18.2, 0) normal (0, 1, 0) x axis (1, 0, 0)
  line L1 (1.6, -19.9) -> (1.6, -9.1)
  line L2 (-1.6, -9.1) -> (-1.6, -19.9)
  arc A1 centre (0, -19.9) radius 1.6 clockwise from (1.6, -19.9) to (-1.6, -19.9)
  arc A2 centre (0, -9.1) radius 1.6 clockwise from (-1.6, -9.1) to (1.6, -9.1)
extrude "Extrude3" cut sketch "SK_Cradle_Right_Slot" distance 2
copy_paste "CopyPaste1"
place_component sketch "SK_PCB_Substrate"
work_plane "WorkPlane1" AlongDistance 1 ExtraOffset 0
sketch "SK_Isolation_Pad_Body" plane through (0, 0, 1) normal (0, 0, 1) x axis (1, 0, 0)
  line L1 (81, -31) -> (19, -31)
  line L2 (81, 1) -> (81, -31)
  line L3 (19, 1) -> (81, 1)
  line L4 (19, -31) -> (19, 1)
extrude "Extrude1" new body sketch "SK_Isolation_Pad_Body" along normal blind 2
work_plane "WorkPlane2" AlongDistance 1 ExtraOffset 0
sketch "SK_Iso_Pad_Vent_Slot" plane through (0, 0, 1) normal (0, 0, 1) x axis (1, 0, 0)
  line L1 (64, -12) -> (36, -12)
  line L2 (36, -18) -> (64, -18)
  arc A1 centre (64, -15) radius 3 clockwise from (64, -12) to (64, -18)
  arc A2 centre (36, -15) radius 3 clockwise from (36, -18) to (36, -12)
extrude "Extrude2" cut sketch "SK_Iso_Pad_Vent_Slot" distance 3
work_plane "WorkPlane1" AlongDistance -2.5 ExtraOffset 0
sketch "SK_Retention_Strap_U" plane through (-2.5, 0, 0) normal (1, 0, 0) x axis (0, 0, -1)
  line L1 (-13.5, -18.3) -> (-13.5, -19.3)
  line L2 (-27.2, -18.3) -> (-13.5, -18.3)
  line L3 (-27.2, 18.3) -> (-27.2, -18.3)
  line L4 (-13.5, 18.3) -> (-27.2, 18.3)
  line L5 (-13.5, 19.3) -> (-13.5, 18.3)
  line L6 (-28.2, 19.3) -> (-13.5, 19.3)
  line L7 (-28.2, -19.3) -> (-28.2, 19.3)
  line L8 (-13.5, -19.3) -> (-28.2, -19.3)
extrude "Extrude1" new body sketch "SK_Retention_Strap_U" along normal blind 5
copy_paste "CopyPaste2"
place_component sketch "SK_PCB_Substrate"
work_plane "WorkPlane1" AlongDistance 177.85 ExtraOffset 0
sketch "SK_Connector_Plate_Blank" plane through (177.85, 0, 0) normal (1, 0, 0) x axis (0, 0, -1)
  line L1 (-14, 33) -> (-14, -33)
  line L2 (-38.5, 33) -> (-14, 33)
  line L3 (-38.5, -33) -> (-38.5, 33)
  line L4 (-14, -33) -> (-38.5, -33)
face "BaseFlange2" sketch "SK_Connector_Plate_Blank"
sketch "SK_Connector_Plate_Cutouts" plane through (177.85, 0, 0) normal (1, 0, 0) x axis (0, 0, -1)
  line L1 (-22, 5.5) -> (-22, -5.5)
  line L2 (-28, 5.5) -> (-22, 5.5)
  line L3 (-28, -5.5) -> (-28, 5.5)
  line L4 (-22, -5.5) -> (-28, -5.5)
  circle C1 centre (-18, -28.5) radius 1.1
  circle C2 centre (-34, -28.5) radius 1.1
  circle C3 centre (-18, 28.5) radius 1.1
  circle C4 centre (-34, 28.5) radius 1.1
  circle C5 centre (-25, -16) radius 4.5
  circle C6 centre (-25, 16) radius 4.5
  circle C7 centre (-25, -7) radius 1.1
  circle C8 centre (-25, 7) radius 1.1
extrude "Extrude1" cut sketch "SK_Connector_Plate_Cutouts" distance 2
sketch "SK_Conn_Flange" plane through (0, 0, 0) normal (0, 0, 1) x axis (1, 0, 0)
  circle C1 centre (0, 0) radius 6.25
extrude "Extrude1" new body sketch "SK_Conn_Flange" along a picked direction blind 1.5
work_plane "WorkPlane1" AlongDistance -2.6 ExtraOffset 0
sketch "SK_Conn_Rear_Body" plane through (0, 0, -2.6) normal (0, 0, 1) x axis (1, 0, 0)
  circle C1 centre (0, 0) radius 4.4
extrude "Extrude2" add sketch "SK_Conn_Rear_Body" along a picked direction blind 2.6
work_plane "WorkPlane2" AlongDistance 1.5 ExtraOffset 0
sketch "SK_Conn_Mating_Barrel" plane through (0, 0, 1.5) normal (0, 0, 1) x axis (1, 0, 0)
  circle C1 centre (0, 0) radius 4.5
  circle C2 centre (0, 0) radius 3.1
extrude "Extrude3" add sketch "SK_Conn_Mating_Barrel" along a picked direction blind 4.5
copy_paste "CopyPaste1"
place_component sketch "SK_PCB_Substrate"
work_plane "WorkPlane1" AlongDistance 20.5 ExtraOffset 0
sketch "SK_MicroD_Flange" plane through (0, 0, 20.5) normal (0, 0, 1) x axis (1, 0, 0)
  line L1 (179.35, -8.5) -> (177.85, -8.5)
  line L2 (179.35, 8.5) -> (179.35, -8.5)
  line L3 (177.85, 8.5) -> (179.35, 8.5)
  line L4 (177.85, -8.5) -> (177.85, 8.5)
extrude "Extrude1" new body sketch "SK_MicroD_Flange" along normal blind 9
work_plane "WorkPlane2" AlongDistance 22.1 ExtraOffset 0
sketch "SK_MicroD_Rear_Body" plane through (0, 0, 22.1) normal (0, 0, 1) x axis (1, 0, 0)
  line L1 (177.85, -5.4) -> (175.25, -5.4)
  line L2 (177.85, 5.4) -> (177.85, -5.4)
  line L3 (175.25, 5.4) -> (177.85, 5.4)
  line L4 (175.25, -5.4) -> (175.25, 5.4)
extrude "Extrude2" add sketch "SK_MicroD_Rear_Body" along normal blind 5.8
work_plane "WorkPlane3" AlongDistance 22.1 ExtraOffset 0
sketch "SK_MicroD_Shroud" plane through (0, 0, 22.1) normal (0, 0, 1) x axis (1, 0, 0)
  line L1 (183.05, -5.4) -> (179.35, -5.4)
  line L2 (183.05, 5.4) -> (183.05, -5.4)
  line L3 (179.35, 5.4) -> (183.05, 5.4)
  line L4 (179.35, -5.4) -> (179.35, 5.4)
extrude "Extrude3" add sketch "SK_MicroD_Shroud" along normal blind 5.8
work_plane "WorkPlane4" AlongDistance 23.1 ExtraOffset 0
sketch "SK_MicroD_Pin_Pocket" plane through (0, 0, 23.1) normal (0, 0, 1) x axis (1, 0, 0)
  line L1 (183.45, -4.4) -> (180.25, -4.4)
  line L2 (183.45, 4.4) -> (183.45, -4.4)
  line L3 (180.25, 4.4) -> (183.45, 4.4)
  line L4 (180.25, -4.4) -> (180.25, 4.4)
extrude "Extrude4" cut sketch "SK_MicroD_Pin_Pocket" along normal blind 3.8
work_plane "WorkPlane5" AlongDistance 177.85 ExtraOffset 0
sketch "SK_MicroD_Jackposts" plane through (177.85, 0, 0) normal (1, 0, 0) x axis (0, 0, -1)
  circle C1 centre (-25, -7) radius 1.1
  circle C2 centre (-25, 7) radius 1.1
extrude "Extrude5" cut sketch "SK_MicroD_Jackposts" distance 2.5
place_component sketch "SK_PCB_Substrate"
work_plane "WorkPlane1" AlongDistance 176.85 ExtraOffset 0
sketch "SK_Strain_Relief_Blank" plane through (176.85, 0, 0) normal (1, 0, 0) x axis (0, 0, -1)
  line L1 (-31.8, 32) -> (-31.8, -32)
  line L2 (-38.5, 32) -> (-31.8, 32)
  line L3 (-38.5, -32) -> (-38.5, 32)
  line L4 (-31.8, -32) -> (-38.5, -32)
face "BaseFlange2" sketch "SK_Strain_Relief_Blank"
face "EdgeFlange3" FlangeHeight 8 FlangeAngle 90
sketch "SK_Strain_Relief_Mount_Holes" plane through (176.85, 0, 0) normal (1, 0, 0) x axis (0, 0, -1)
  circle C1 centre (-34, -28.5) radius 1.1
  circle C2 centre (-34, 28.5) radius 1.1
extrude "Extrude1" cut sketch "SK_Strain_Relief_Mount_Holes" distance 2
work_plane "WorkPlane2" AlongDistance 38.5 ExtraOffset 0
sketch "SK_Strain_Relief_Tie_Slots" plane through (0, 0, 38.5) normal (0, 0, 1) x axis (1, 0, 0)
  line L1 (173.25, -14.25) -> (173.25, -17.75)
  line L2 (170.75, -17.75) -> (170.75, -14.25)
  line L3 (173.25, 1.75) -> (173.25, -1.75)
  line L4 (170.75, -1.75) -> (170.75, 1.75)
  line L5 (173.25, 17.75) -> (173.25, 14.25)
  line L6 (170.75, 14.25) -> (170.75, 17.75)
  arc A1 centre (172, -14.25) radius 1.25 clockwise from (170.75, -14.25) to (173.25, -14.25)
  arc A2 centre (172, -17.75) radius 1.25 clockwise from (173.25, -17.75) to (170.75, -17.75)
  arc A3 centre (172, 1.75) radius 1.25 clockwise from (170.75, 1.75) to (173.25, 1.75)
  arc A4 centre (172, -1.75) radius 1.25 clockwise from (173.25, -1.75) to (170.75, -1.75)
  arc A5 centre (172, 17.75) radius 1.25 clockwise from (170.75, 17.75) to (173.25, 17.75)
  arc A6 centre (172, 14.25) radius 1.25 clockwise from (173.25, 14.25) to (170.75, 14.25)
extrude "Extrude2" cut sketch "SK_Strain_Relief_Tie_Slots" distance 2
place_component sketch "SK_PCB_Substrate"
work_plane "WorkPlane1" AlongDistance 1 ExtraOffset 0
sketch "SK_Cable_Channel_Blank" plane through (0, 0, 1) normal (0, 0, 1) x axis (1, 0, 0)
  line L1 (166, 8.5) -> (98, 8.5)
  line L2 (166, 21.5) -> (166, 8.5)
  line L3 (98, 21.5) -> (166, 21.5)
  line L4 (98, 8.5) -> (98, 21.5)
face "BaseFlange1" sketch "SK_Cable_Channel_Blank"
face "EdgeFlange2" FlangeHeight 5 FlangeAngle 90
sketch "SK_Cable_Channel_Holes" plane through (0, 0, 1) normal (0, 0, 1) x axis (1, 0, 0)
  circle C1 centre (112, 12.5) radius 1.1
  circle C2 centre (152, 12.5) radius 1.1
extrude "Extrude1" cut sketch "SK_Cable_Channel_Holes" distance 2
sketch "SK_Cable_Clamp_Blank" plane through (0, 0, 0) normal (0, 0, 1) x axis (1, 0, 0)
  line L1 (3.5, -6.5) -> (-3.5, -6.5)
  line L2 (3.5, 4.5) -> (3.5, -6.5)
  line L3 (-3.5, 4.5) -> (3.5, 4.5)
  line L4 (-3.5, -6.5) -> (-3.5, 4.5)
face "BaseFlange1" sketch "SK_Cable_Clamp_Blank"
face "EdgeFlange2" FlangeHeight 5 FlangeAngle 90
face "EdgeFlange3" FlangeHeight 5 FlangeAngle 90
sketch "SK_Cable_Clamp_Hole" plane through (0, 0, 0) normal (0, 0, 1) x axis (1, 0, 0)
  circle C1 centre (0, -2.5) radius 1.1
extrude "Extrude1" cut sketch "SK_Cable_Clamp_Hole" distance 2
copy_paste "CopyPaste1"
copy_paste "CopyPaste2"
place_component sketch "SK_PCB_Substrate"
work_plane "WorkPlane1" AlongDistance 17.5 ExtraOffset 0
sketch "SK_PDB-07-703_Power_Harness_Visual_Path" plane through (0, 17.5, 0) normal (0, 1, 0) x axis (1, 0, 0)
  line L1 (171.2, -3.2) -> (48.5, -3.2)
  line L2 (175.2, -20.4) -> (175.2, -7.2)
  arc A1 centre (171.2, -7.2) radius 4 clockwise from (171.2, -3.2) to (175.2, -7.2)
work_plane "WorkPlane2" AlongDistance 48.5 ExtraOffset 0
sketch "SK_PDB-07-703_Power_Harness_Visual_Profile" plane through (48.5, 0, 0) normal (1, 0, 0) x axis (0, 0, -1)
  circle C1 centre (-3.2, 17.5) radius 1
sweep "Sweep1" sketch "SK_PDB-07-703_Power_Harness_Visual_Profile" TwistAngle 0 TaperAngle 0
place_component sketch "SK_PCB_Substrate"
work_plane "WorkPlane1" AlongDistance -13.5 ExtraOffset 0
sketch "SK_PDB-07-704_Signal_Harness_Visual_Path" plane through (0, -13.5, 0) normal (0, 1, 0) x axis (1, 0, 0)
  line L1 (171.2, -3) -> (104, -3)
  line L2 (175.2, -20.4) -> (175.2, -7)
  arc A1 centre (171.2, -7) radius 4 clockwise from (171.2, -3) to (175.2, -7)
work_plane "WorkPlane2" AlongDistance 104 ExtraOffset 0
sketch "SK_PDB-07-704_Signal_Harness_Visual_Profile" plane through (104, 0, 0) normal (1, 0, 0) x axis (0, 0, -1)
  circle C1 centre (-3, -13.5) radius 1
sweep "Sweep1" sketch "SK_PDB-07-704_Signal_Harness_Visual_Profile" TwistAngle 0 TaperAngle 0
sketch "SK_Fastener_Head" plane through (0, 0, 0) normal (0, 0, 1) x axis (1, 0, 0)
  circle C1 centre (0, 0) radius 2.25
extrude "Extrude1" new body sketch "SK_Fastener_Head" along a picked direction blind 1.2
sketch "SK_Fastener_Shank" plane through (0, 0, 0) normal (0, 0, 1) x axis (1, 0, 0)
  circle C1 centre (0, 0) radius 1.25
extrude "Extrude2" add sketch "SK_Fastener_Shank" along a picked direction blind -5
copy_paste "CopyPaste1"
copy_paste "CopyPaste2"
copy_paste "CopyPaste3"
copy_paste "CopyPaste4"
copy_paste "CopyPaste5"
copy_paste "CopyPaste6"
copy_paste "CopyPaste7"
copy_paste "CopyPaste8"
copy_paste "CopyPaste9"
copy_paste "CopyPaste10"
copy_paste "CopyPaste11"
copy_paste "CopyPaste12"
copy_paste "CopyPaste13"
copy_paste "CopyPaste14"
copy_paste "CopyPaste15"
copy_paste "CopyPaste16"
copy_paste "CopyPaste17"
copy_paste "CopyPaste18"
copy_paste "CopyPaste19"
copy_paste "CopyPaste20"
copy_paste "CopyPaste21"
copy_paste "CopyPaste22"
copy_paste "CopyPaste23"
copy_paste "CopyPaste24"
copy_paste "CopyPaste25"
copy_paste "CopyPaste26"
copy_paste "CopyPaste27"
copy_paste "CopyPaste28"
copy_paste "CopyPaste29"
copy_paste "CopyPaste30"
copy_paste "CopyPaste31"
place_component sketch "SK_Hardware_Ring"
sketch "SK_Hardware_Ring" plane through (0, 0, 0) normal (0, 0, 1) x axis (1, 0, 0)
  circle C1 centre (0, 0) radius 2.75
  circle C2 centre (0, 0) radius 1.35
extrude "Extrude1" new body sketch "SK_Hardware_Ring" along normal blind 0.5
copy_paste "CopyPaste32"
copy_paste "CopyPaste33"
copy_paste "CopyPaste34"
copy_paste "CopyPaste35"
copy_paste "CopyPaste36"
copy_paste "CopyPaste37"
copy_paste "CopyPaste38"
copy_paste "CopyPaste39"
copy_paste "CopyPaste40"
copy_paste "CopyPaste41"
copy_paste "CopyPaste42"
place_component sketch "SK_Hardware_Ring"
sketch "SK_Hardware_Ring" plane through (0, 0, 0) normal (0, 0, 1) x axis (1, 0, 0)
  circle C1 centre (0, 0) radius 2.5
  circle C2 centre (0, 0) radius 1.25
extrude "Extrude1" new body sketch "SK_Hardware_Ring" along a picked direction blind 2
copy_paste "CopyPaste43"
copy_paste "CopyPaste44"
copy_paste "CopyPaste45"
copy_paste "CopyPaste46"
copy_paste "CopyPaste47"
copy_paste "CopyPaste48"
copy_paste "CopyPaste49"
copy_paste "CopyPaste50"
copy_paste "CopyPaste51"
copy_paste "CopyPaste52"
copy_paste "CopyPaste53"
copy_paste "CopyPaste54"
copy_paste "CopyPaste55"
copy_paste "CopyPaste56"
copy_paste "CopyPaste57"
copy_paste "CopyPaste58"
copy_paste "CopyPaste59"
copy_paste "CopyPaste60"
copy_paste "CopyPaste61"
copy_paste "CopyPaste62"
copy_paste "CopyPaste63"
copy_paste "CopyPaste64"
copy_paste "CopyPaste65"
sketch "SK_Fastener_Head" plane through (0, 0, 0) normal (0, 0, 1) x axis (1, 0, 0)
  circle C1 centre (0, 0) radius 1.8
extrude "Extrude1" new body sketch "SK_Fastener_Head" along normal blind 0.9
sketch "SK_Fastener_Shank" plane through (0, 0, 0) normal (0, 0, 1) x axis (1, 0, 0)
  circle C1 centre (0, 0) radius 1
extrude "Extrude2" add sketch "SK_Fastener_Shank" against normal blind 4
copy_paste "CopyPaste66"
copy_paste "CopyPaste67"
copy_paste "CopyPaste68"
copy_paste "CopyPaste69"
copy_paste "CopyPaste70"
copy_paste "CopyPaste71"
copy_paste "CopyPaste72"
copy_paste "CopyPaste73"
copy_paste "CopyPaste74"
copy_paste "CopyPaste75"
copy_paste "CopyPaste76"
copy_paste "CopyPaste77"
copy_paste "CopyPaste78"
copy_paste "CopyPaste79"
copy_paste "CopyPaste80"
copy_paste "CopyPaste81"
copy_paste "CopyPaste82"
copy_paste "CopyPaste83"
copy_paste "CopyPaste84"
copy_paste "CopyPaste85"
copy_paste "CopyPaste86"
copy_paste "CopyPaste87"
copy_paste "CopyPaste88"
place_component sketch "SK_Hardware_Ring"
sketch "SK_Hardware_Ring" plane through (0, 0, 0) normal (0, 0, 1) x axis (1, 0, 0)
  circle C1 centre (0, 0) radius 2.25
  circle C2 centre (0, 0) radius 1.05
extrude "Extrude1" new body sketch "SK_Hardware_Ring" along normal blind 0.8
copy_paste "CopyPaste89"
copy_paste "CopyPaste90"
copy_paste "CopyPaste91"
copy_paste "CopyPaste92"
copy_paste "CopyPaste93"
copy_paste "CopyPaste94"
copy_paste "CopyPaste95"
sketch "SK_Fastener_Head" plane through (0, 0, 0) normal (0, 0, 1) x axis (1, 0, 0)
  circle C1 centre (0, 0) radius 1.8
extrude "Extrude1" new body sketch "SK_Fastener_Head" along normal blind 0.9
sketch "SK_Fastener_Shank" plane through (0, 0, 0) normal (0, 0, 1) x axis (1, 0, 0)
  circle C1 centre (0, 0) radius 1
extrude "Extrude2" add sketch "SK_Fastener_Shank" against normal blind 3
copy_paste "CopyPaste96"
copy_paste "CopyPaste97"
copy_paste "CopyPaste98"
copy_paste "CopyPaste99"
copy_paste "CopyPaste100"
copy_paste "CopyPaste101"
copy_paste "CopyPaste102"
sketch "SK_Fastener_Head" plane through (0, 0, 0) normal (0, 0, 1) x axis (1, 0, 0)
  circle C1 centre (0, 0) radius 1.8
extrude "Extrude1" new body sketch "SK_Fastener_Head" along normal blind 0.6
sketch "SK_Fastener_Shank" plane through (0, 0, 0) normal (0, 0, 1) x axis (1, 0, 0)
  circle C1 centre (0, 0) radius 1
extrude "Extrude2" add sketch "SK_Fastener_Shank" against normal blind 1.8
copy_paste "CopyPaste103"
copy_paste "CopyPaste104"
copy_paste "CopyPaste105"
copy_paste "CopyPaste106"
copy_paste "CopyPaste107"
copy_paste "CopyPaste108"
copy_paste "CopyPaste109"
copy_paste "CopyPaste110"
sketch "SK_Fastener_Head" plane through (0, 0, 0) normal (0, 0, 1) x axis (1, 0, 0)
  circle C1 centre (0, 0) radius 2.25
